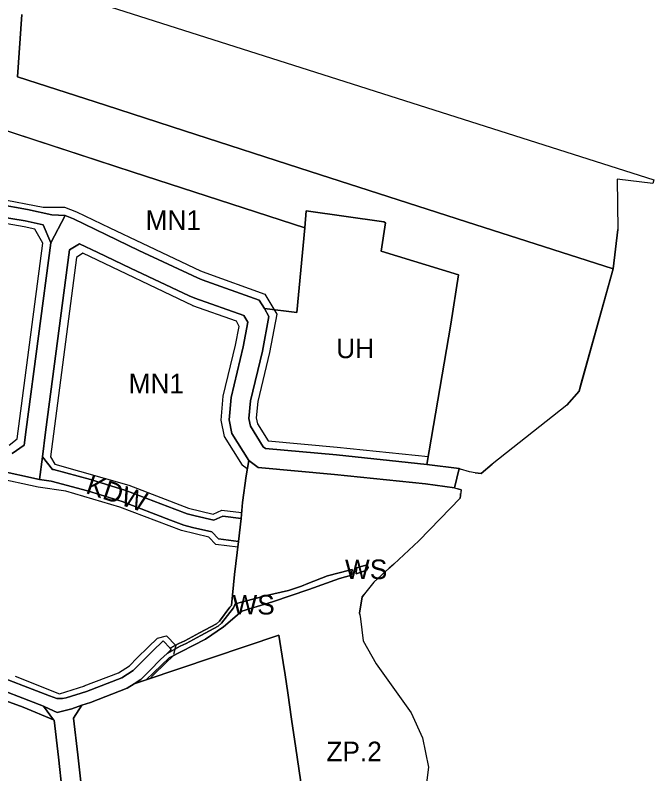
# Model space of a CAD drawing. Extents: x 7417187 to 7419415, y 5539178 to 5540826.
# Drawn here: x 7419039.6 to 7419365.1, y 5539846.6 to 5540233.3 of the extents above; entities that cross this region are included whole.
import ezdxf

# ---------------------------------------------------------------- set-up
doc = ezdxf.new("R2010")
doc.units = 0
for name, color, linetype in [('linie_rozgraniczajace', 7, 'Continuous'), ('linie_zabudowy_nieprzekraczalne', 7, 'Continuous'), ('oznaczenia_przeznaczen', 7, 'Continuous')]:
    doc.layers.add(name, color=color, linetype=linetype)

msp = doc.modelspace()

# ---------------------------------------------------------------- linework, layer by layer
at = {"layer": 'linie_rozgraniczajace'}
for p, q in [((7418953.71, 5540280.42), (7419365.07, 5540149.32)), ((7419040.73, 5540201.92), (7419042.99, 5540233.61)), ((7419042.99, 5540233.61), (7419040.73, 5540201.92)), ((7419085.71, 5540187.37), (7419040.73, 5540201.92)), ((7419040.73, 5540201.92), (7419085.71, 5540187.37)), ((7419125.94, 5540174.36), (7419085.71, 5540187.37)), ((7419085.71, 5540187.37), (7419125.94, 5540174.36)), ((7419099.77, 5540153.28), (7419009.97, 5540182.65)), ((7419189.96, 5540153.67), (7419125.94, 5540174.36)), ((7419125.94, 5540174.36), (7419189.96, 5540153.67)), ((7419187.3, 5540124.89), (7419099.77, 5540153.28)), ((7419269.53, 5540127.96), (7419189.96, 5540153.67)), ((7419189.96, 5540153.67), (7419269.53, 5540127.96)), ((7419364.59, 5540147.43), (7419346.47, 5540149.69)), ((7419346.47, 5540149.69), (7419346.66, 5540124.04)), ((7419365.07, 5540149.32), (7419364.59, 5540147.43)), ((7419187.88, 5540133.63), (7419187.3, 5540124.89)), ((7419227.45, 5540128), (7419187.88, 5540133.63)), ((7419226.14, 5540113.01), (7419228.27, 5540127.52)), ((7419228.27, 5540127.52), (7419227.45, 5540128)), ((7419344.29, 5540103.93), (7419269.53, 5540127.96)), ((7419269.53, 5540127.96), (7419344.29, 5540103.93)), ((7419346.66, 5540124.04), (7419344.29, 5540103.93)), ((7419344.29, 5540103.93), (7419346.66, 5540124.04)), ((7419346.66, 5540124.04), (7419344.29, 5540103.91)), ((7419265.58, 5540100.95), (7419226.14, 5540113.01)), ((7419344.29, 5540103.91), (7419326.95, 5540041.57)), ((7419344.29, 5540103.93), (7419327.75, 5540044.48)), ((7419327.75, 5540044.48), (7419344.29, 5540103.91)), ((7419344.29, 5540103.91), (7419344.29, 5540103.93)), ((7419261.62, 5540075.72), (7419265.58, 5540100.95)), ((7419249.35, 5540004.33), (7419261.62, 5540075.72)), ((7419326.99, 5540041.72), (7419327.75, 5540044.48)), ((7419327.75, 5540044.48), (7419326.99, 5540041.72)), ((7419326.95, 5540041.57), (7419320.75, 5540034.55)), ((7419320.75, 5540034.55), (7419326.95, 5540041.57)), ((7419326.95, 5540041.57), (7419320.75, 5540034.55)), ((7419326.95, 5540041.57), (7419326.99, 5540041.72)), ((7419326.99, 5540041.72), (7419326.95, 5540041.57)), ((7419320.75, 5540034.55), (7419282.67, 5540004.35)), ((7419157.28, 5539998.44), (7419158.63, 5540006.28)), ((7419158.63, 5540006.28), (7419163.52, 5540002.66)), ((7419163.52, 5540002.66), (7419202.39, 5539999.21)), ((7419265.81, 5540002.21), (7419249.35, 5540004.33)), ((7419265.81, 5540002.21), (7419263.58, 5539992.41)), ((7419263.58, 5539992.41), (7419265.81, 5540002.21)), ((7419266.52, 5540001.97), (7419265.81, 5540002.21)), ((7419265.81, 5540002.21), (7419266.52, 5540001.97)), ((7419266.52, 5540001.97), (7419265.81, 5540002.21)), ((7419271.11, 5540000.46), (7419266.52, 5540001.97)), ((7419282.67, 5540004.35), (7419277.05, 5539999.71)), ((7419277.05, 5539999.71), (7419282.67, 5540004.35)), ((7419282.67, 5540004.35), (7419277.05, 5539999.71)), ((7419155.44, 5539984.94), (7419157.28, 5539998.44)), ((7419202.39, 5539999.21), (7419248.75, 5539994.34)), ((7419274.04, 5540000.09), (7419271.11, 5540000.46)), ((7419277.05, 5539999.71), (7419274.04, 5540000.09)), ((7419277.05, 5539999.71), (7419274.04, 5540000.09)), ((7419274.04, 5540000.09), (7419277.05, 5539999.71)), ((7419248.75, 5539994.34), (7419263.58, 5539992.41)), ((7419263.58, 5539992.41), (7419263.58, 5539992.41)), ((7419263.58, 5539992.41), (7419265.23, 5539991.87)), ((7419265.23, 5539991.87), (7419266.89, 5539991.32)), ((7419266.89, 5539991.32), (7419265.23, 5539991.87)), ((7419265.23, 5539991.87), (7419266.89, 5539991.32)), ((7419266.35, 5539987.16), (7419256.18, 5539976.58)), ((7419266.35, 5539987.16), (7419256.18, 5539976.58)), ((7419256.18, 5539976.58), (7419266.35, 5539987.16)), ((7419266.64, 5539989.41), (7419266.35, 5539987.16)), ((7419266.51, 5539988.44), (7419266.35, 5539987.16)), ((7419266.35, 5539987.16), (7419266.51, 5539988.44)), ((7419266.64, 5539989.41), (7419266.51, 5539988.44)), ((7419266.51, 5539988.44), (7419266.64, 5539989.41)), ((7419154.75, 5539976.78), (7419155.44, 5539984.94)), ((7419153.45, 5539965.06), (7419154.75, 5539976.78)), ((7419256.18, 5539976.58), (7419245.31, 5539965.31)), ((7419256.18, 5539976.58), (7419245.31, 5539965.31)), ((7419245.31, 5539965.31), (7419256.18, 5539976.58)), ((7419151.33, 5539948.18), (7419153.45, 5539965.06)), ((7419245.31, 5539965.31), (7419232.56, 5539953.41)), ((7419245.31, 5539965.31), (7419232.56, 5539953.41)), ((7419232.56, 5539953.41), (7419245.31, 5539965.31)), ((7419213.56, 5539951.52), (7419213.39, 5539948.58)), ((7419218.94, 5539953.17), (7419213.56, 5539951.52)), ((7419218.6, 5539950.37), (7419219.44, 5539951.71)), ((7419219.44, 5539951.71), (7419218.94, 5539953.17)), ((7419230.26, 5539951.36), (7419222.43, 5539944.35)), ((7419232.56, 5539953.41), (7419230.26, 5539951.36)), ((7419230.49, 5539951.56), (7419230.26, 5539951.36)), ((7419230.26, 5539951.36), (7419230.49, 5539951.56)), ((7419232.56, 5539953.41), (7419230.49, 5539951.56)), ((7419230.49, 5539951.56), (7419232.56, 5539953.41)), ((7419149.86, 5539932.35), (7419151.33, 5539948.18)), ((7419198.73, 5539947.49), (7419188.69, 5539943.59)), ((7419209.91, 5539950.4), (7419198.73, 5539947.49)), ((7419204.89, 5539946.22), (7419211.08, 5539947.94)), ((7419211.27, 5539950.81), (7419209.91, 5539950.4)), ((7419211.08, 5539947.94), (7419211.27, 5539950.81)), ((7419213.39, 5539948.58), (7419214.91, 5539949)), ((7419214.91, 5539949), (7419218.6, 5539950.37)), ((7419188.69, 5539943.59), (7419185.46, 5539942.26)), ((7419189.3, 5539940.52), (7419204.89, 5539946.22)), ((7419222.43, 5539944.35), (7419217.63, 5539938.3)), ((7419178.91, 5539940.12), (7419167.69, 5539937.51)), ((7419170.7, 5539934.34), (7419189.3, 5539940.52)), ((7419185.46, 5539942.26), (7419178.91, 5539940.12)), ((7419167.69, 5539937.51), (7419155.72, 5539934.3)), ((7419216.52, 5539936.9), (7419215.12, 5539928.42)), ((7419216.52, 5539936.9), (7419215.12, 5539928.42)), ((7419215.12, 5539928.42), (7419216.52, 5539936.9)), ((7419217.63, 5539938.3), (7419216.52, 5539936.9)), ((7419217.43, 5539938.05), (7419216.52, 5539936.9)), ((7419216.52, 5539936.9), (7419217.43, 5539938.05)), ((7419217.63, 5539938.3), (7419217.43, 5539938.05)), ((7419217.43, 5539938.05), (7419217.63, 5539938.3)), ((7419149.02, 5539931.48), (7419149.86, 5539932.35)), ((7419151.76, 5539933.27), (7419150.82, 5539931.15)), ((7419155.72, 5539934.3), (7419151.76, 5539933.27)), ((7419155.11, 5539929.59), (7419170.7, 5539934.34)), ((7419143.68, 5539924.38), (7419149.02, 5539931.48)), ((7419150.82, 5539931.15), (7419144.8, 5539923.37)), ((7419145.85, 5539921.58), (7419155.11, 5539929.59)), ((7419215.12, 5539928.42), (7419215.12, 5539928.42)), ((7419215.12, 5539928.42), (7419215.21, 5539927.85)), ((7419215.12, 5539928.42), (7419215.12, 5539928.42)), ((7419215.12, 5539928.42), (7419215.21, 5539927.85)), ((7419215.21, 5539927.85), (7419215.12, 5539928.42)), ((7419142.26, 5539923.02), (7419143.68, 5539924.38)), ((7419215.21, 5539927.85), (7419215.59, 5539925.62)), ((7419215.59, 5539925.62), (7419216.9, 5539914.34)), ((7419133.48, 5539918.5), (7419142.26, 5539923.02)), ((7419143.14, 5539921.79), (7419134.18, 5539917.17)), ((7419136.54, 5539915.24), (7419145.85, 5539921.58)), ((7419144.8, 5539923.37), (7419143.14, 5539921.79)), ((7419174.03, 5539917.24), (7419106.41, 5539894.54)), ((7419126.05, 5539914.46), (7419133.48, 5539918.5)), ((7419134.18, 5539917.17), (7419126.72, 5539913.11)), ((7419176.19, 5539903.36), (7419174.03, 5539917.24)), ((7419118.13, 5539905.71), (7419136.54, 5539915.24)), ((7419118.62, 5539910.59), (7419123.01, 5539913.09)), ((7419123.01, 5539913.09), (7419126.05, 5539914.46)), ((7419126.72, 5539913.11), (7419123.69, 5539911.75)), ((7419216.9, 5539914.34), (7419223.57, 5539902.66)), ((7419123.69, 5539911.75), (7419117, 5539907.94)), ((7419117, 5539907.94), (7419119.17, 5539910.02)), ((7419119.17, 5539910.02), (7419118.62, 5539910.59)), ((7419106.41, 5539894.54), (7419118.13, 5539905.71)), ((7419177.17, 5539896.99), (7419176.19, 5539903.36)), ((7419223.57, 5539902.66), (7419241.45, 5539877.63)), ((7419178.5, 5539887.94), (7419177.17, 5539896.99)), ((7419180.45, 5539874.45), (7419178.5, 5539887.94)), ((7419241.45, 5539877.63), (7419247.22, 5539864.94)), ((7419182.59, 5539859.62), (7419180.45, 5539874.45)), ((7419247.22, 5539864.94), (7419250.22, 5539850.01)), ((7419185.79, 5539837.72), (7419182.59, 5539859.62)), ((7419250.22, 5539850.01), (7419249.03, 5539840.61))]:
    msp.add_line(p, q, dxfattribs=at)
for points in [[(7419009.97, 5540182.65), (7419099.77, 5540153.28), (7419187.3, 5540124.89), (7419183.16, 5540081.78), (7419166.6, 5540083.72), (7419164.04, 5540088.08), (7419134.86, 5540098.32), (7419132.48, 5540099.36), (7419102.61, 5540113.38), (7419086.16, 5540121.29), (7419069.34, 5540129.44), (7419065.02, 5540131.1), (7419058.27, 5540131.55), (7419045.91, 5540134.3), (7419030.57, 5540136.87)], [(7419030.57, 5540136.87), (7419045.91, 5540134.3), (7419058.27, 5540131.55), (7419065.02, 5540131.1), (7419057.79, 5540117.26), (7419053.89, 5540126.4), (7419044.7, 5540128.42), (7419029.99, 5540130.9)], [(7419029.99, 5540130.9), (7419044.7, 5540128.42), (7419053.89, 5540126.4), (7419057.79, 5540117.26), (7419045.21, 5540022.08), (7419044.21, 5540014.19), (7419038.11, 5540009.87)], [(7419038.11, 5540009.87), (7419044.21, 5540014.19), (7419045.21, 5540022.08), (7419057.79, 5540117.26), (7419065.02, 5540131.1), (7419069.34, 5540129.44), (7419086.16, 5540121.29), (7419102.61, 5540113.38), (7419132.48, 5540099.36), (7419134.86, 5540098.32), (7419164.04, 5540088.08), (7419166.6, 5540083.72), (7419168.93, 5540079.77), (7419165.58, 5540062.1), (7419159.54, 5540036.74), (7419158.69, 5540027.63), (7419159.49, 5540023.81), (7419166.05, 5540013.22), (7419167.2, 5540012.38), (7419203.35, 5540009.16), (7419249.35, 5540004.33), (7419265.81, 5540002.21), (7419263.58, 5539992.41), (7419248.75, 5539994.34), (7419202.39, 5539999.21), (7419163.52, 5540002.66), (7419158.63, 5540006.28), (7419150.06, 5540020.04), (7419148.6, 5540027.06), (7419149.65, 5540038.37), (7419155.8, 5540064.19), (7419158.19, 5540076.8), (7419156.16, 5540080.25), (7419131.19, 5540089.01), (7419128.35, 5540090.25), (7419098.32, 5540104.35), (7419081.81, 5540112.28), (7419072.47, 5540116.81), (7419067.39, 5540113.62), (7419055.12, 5540020.79), (7419053.54, 5540008.24), (7419052.07, 5539996.64), (7419051.98, 5539996.65), (7419030.26, 5540001.34)], [(7419030.26, 5540001.34), (7419051.98, 5539996.65), (7419052.07, 5539996.64), (7419057.95, 5539995.77), (7419076.43, 5539990.84), (7419094.12, 5539985.36), (7419118.75, 5539975.96), (7419125.51, 5539973.32), (7419129.92, 5539972.22), (7419139.78, 5539969.93), (7419143.28, 5539966.35), (7419153.45, 5539965.06), (7419151.33, 5539948.18), (7419149.86, 5539932.35), (7419149.02, 5539931.48), (7419143.68, 5539924.38), (7419142.26, 5539923.02), (7419133.48, 5539918.5), (7419126.05, 5539914.46), (7419123.01, 5539913.09), (7419118.62, 5539910.59), (7419115.02, 5539914.35), (7419109.53, 5539909.09), (7419103.93, 5539903.54), (7419099.83, 5539899.31), (7419094.01, 5539895.61), (7419075.96, 5539888.61), (7419065.68, 5539885.34), (7419063.76, 5539885.06), (7419060.91, 5539885.08), (7419057.16, 5539886.31), (7419025.25, 5539898.66)], [(7418705.75, 5539931.19), (7418748.43, 5539931.6), (7418756.83, 5539934.88), (7418779.73, 5539935.88), (7418838.4, 5539938.54), (7418861.65, 5539939.62), (7418902.71, 5539935.29), (7418948.05, 5539929.8), (7418949.36, 5539928.49), (7418958.82, 5539916.51), (7418967.84, 5539910.9), (7418990.65, 5539900.55), (7419019.82, 5539889.33), (7419043.74, 5539880.5), (7419059.22, 5539874.18), (7419059.44, 5539873.89), (7419061.66, 5539855.14), (7419063.63, 5539837.78)], [(7419025.25, 5539898.66), (7419057.16, 5539886.31), (7419060.91, 5539885.08), (7419063.76, 5539885.06), (7419065.68, 5539885.34), (7419075.96, 5539888.61), (7419094.01, 5539895.61), (7419099.83, 5539899.31), (7419103.93, 5539903.54), (7419109.53, 5539909.09), (7419115.02, 5539914.35), (7419118.62, 5539910.59), (7419119.17, 5539910.02), (7419117, 5539907.94), (7419113.72, 5539904.8), (7419108.2, 5539899.32), (7419103.65, 5539894.63), (7419100.27, 5539892.48), (7419096.73, 5539890.23), (7419077.96, 5539882.95), (7419073.55, 5539881.54), (7419068.52, 5539879.81), (7419060.97, 5539877.95), (7419054.82, 5539880.78), (7419054.07, 5539881.07), (7419023.14, 5539893.05)], [(7419023.14, 5539893.05), (7419054.07, 5539881.07), (7419059.22, 5539874.18), (7419043.74, 5539880.5), (7419019.82, 5539889.33)], [(7419063.63, 5539837.78), (7419061.66, 5539855.14), (7419059.44, 5539873.89), (7419059.22, 5539874.18), (7419054.07, 5539881.07), (7419054.82, 5539880.78), (7419060.97, 5539877.95), (7419068.52, 5539879.81), (7419073.55, 5539881.54), (7419069.37, 5539875.06), (7419071.59, 5539856.29), (7419073.67, 5539837.92)]]:
    msp.add_lwpolyline(points, dxfattribs=at)
for points in [[(7419249.35, 5540004.33), (7419203.35, 5540009.16), (7419167.2, 5540012.38), (7419166.05, 5540013.22), (7419159.49, 5540023.81), (7419158.69, 5540027.63), (7419159.54, 5540036.74), (7419165.58, 5540062.1), (7419168.93, 5540079.77), (7419166.6, 5540083.72), (7419183.16, 5540081.78), (7419187.3, 5540124.89), (7419187.88, 5540133.63), (7419227.45, 5540128), (7419228.27, 5540127.52), (7419226.14, 5540113.01), (7419265.58, 5540100.95), (7419261.62, 5540075.72)], [(7419158.63, 5540006.28), (7419157.28, 5539998.44), (7419155.44, 5539984.94), (7419154.75, 5539976.78), (7419145.37, 5539977.91), (7419140.91, 5539975.82), (7419131.33, 5539978.05), (7419127.34, 5539979.05), (7419120.91, 5539981.56), (7419096.08, 5539991.03), (7419078.09, 5539996.61), (7419059.16, 5540001.66), (7419058.57, 5540001.74), (7419053.54, 5540008.24), (7419055.12, 5540020.79), (7419067.39, 5540113.62), (7419072.47, 5540116.81), (7419081.81, 5540112.28), (7419098.32, 5540104.35), (7419128.35, 5540090.25), (7419131.19, 5540089.01), (7419156.16, 5540080.25), (7419158.19, 5540076.8), (7419155.8, 5540064.19), (7419149.65, 5540038.37), (7419148.6, 5540027.06), (7419150.06, 5540020.04)], [(7419154.75, 5539976.78), (7419153.45, 5539965.06), (7419143.28, 5539966.35), (7419139.78, 5539969.93), (7419129.92, 5539972.22), (7419125.51, 5539973.32), (7419118.75, 5539975.96), (7419094.12, 5539985.36), (7419076.43, 5539990.84), (7419057.95, 5539995.77), (7419052.07, 5539996.64), (7419053.54, 5540008.24), (7419058.57, 5540001.74), (7419059.16, 5540001.66), (7419078.09, 5539996.61), (7419096.08, 5539991.03), (7419120.91, 5539981.56), (7419127.34, 5539979.05), (7419131.33, 5539978.05), (7419140.91, 5539975.82), (7419145.37, 5539977.91)], [(7419214.91, 5539949), (7419213.39, 5539948.58), (7419213.56, 5539951.52), (7419218.94, 5539953.17), (7419219.44, 5539951.71), (7419218.6, 5539950.37)], [(7419106.41, 5539894.54), (7419100.27, 5539892.48), (7419103.65, 5539894.63), (7419108.2, 5539899.32), (7419113.72, 5539904.8), (7419117, 5539907.94), (7419123.69, 5539911.75), (7419126.72, 5539913.11), (7419134.18, 5539917.17), (7419143.14, 5539921.79), (7419144.8, 5539923.37), (7419150.82, 5539931.15), (7419151.76, 5539933.27), (7419155.72, 5539934.3), (7419167.69, 5539937.51), (7419178.91, 5539940.12), (7419185.46, 5539942.26), (7419188.69, 5539943.59), (7419198.73, 5539947.49), (7419209.91, 5539950.4), (7419211.27, 5539950.81), (7419211.08, 5539947.94), (7419204.89, 5539946.22), (7419189.3, 5539940.52), (7419170.7, 5539934.34), (7419155.11, 5539929.59), (7419145.85, 5539921.58), (7419136.54, 5539915.24), (7419118.13, 5539905.71)], [(7419148.72, 5539779.71), (7419082.92, 5539766.9), (7419081.88, 5539777.49), (7419079.76, 5539798.03), (7419076.8, 5539817.26), (7419073.67, 5539837.92), (7419071.59, 5539856.29), (7419069.37, 5539875.06), (7419073.55, 5539881.54), (7419077.96, 5539882.95), (7419096.73, 5539890.23), (7419100.27, 5539892.48), (7419106.41, 5539894.54), (7419174.03, 5539917.24), (7419176.19, 5539903.36), (7419177.17, 5539896.99), (7419178.5, 5539887.94), (7419180.45, 5539874.45), (7419182.59, 5539859.62), (7419185.79, 5539837.72), (7419188.75, 5539817.33), (7419192.83, 5539788.1), (7419151.48, 5539780.24)]]:
    msp.add_lwpolyline(points, close=True, dxfattribs=at)
msp.add_open_spline([(7419266.89, 5539991.32), (7419266.64, 5539989.41)], degree=1, dxfattribs=at)
at = {"layer": 'linie_zabudowy_nieprzekraczalne'}
for points in [[(7418900.67, 5540133.79), (7418963.86, 5540140.82), (7419003.54, 5540142.07), (7419030.8, 5540139.86), (7419053.93, 5540135.47)], [(7419053.93, 5540135.47), (7419064.72, 5540135.5)], [(7419064.72, 5540135.5), (7419070.93, 5540133.12), (7419087.9, 5540124.89), (7419104.33, 5540117), (7419134.14, 5540103), (7419136.72, 5540101.87)], [(7419049.6, 5540124.28), (7419044.13, 5540125.48), (7419029.63, 5540127.92), (7419023.82, 5540128.35)], [(7419053.72, 5540117.02), (7419049.6, 5540124.28)], [(7419040.61, 5540017.43), (7419053.72, 5540117.02)], [(7419070.92, 5540109.79), (7419057.56, 5540008.16)], [(7419074.18, 5540111.92), (7419070.92, 5540109.79)], [(7419130.3, 5540085.08), (7419074.18, 5540111.92)], [(7419136.7, 5540101.88), (7419166.89, 5540091.12)], [(7419166.89, 5540091.12), (7419172.89, 5540080.92)], [(7419152.48, 5540077.3), (7419130.08, 5540085.16)], [(7419172.89, 5540080.92), (7419169.17, 5540061.3), (7419163.23, 5540036.36), (7419162.43, 5540028.05), (7419163.1, 5540024.97), (7419168.49, 5540016.28)], [(7419153.72, 5540074.68), (7419152.48, 5540077.3)], [(7419155.39, 5540003.87), (7419146.29, 5540018.53), (7419144.56, 5540026.83), (7419145.7, 5540039.02), (7419151.89, 5540065.03), (7419153.72, 5540074.68)], [(7419036.62, 5540014.15), (7419040.61, 5540017.43)], [(7419168.49, 5540016.28), (7419203.74, 5540013.14), (7419250.03, 5540008.28)], [(7419057.56, 5540008.16), (7419059.92, 5540004.45)], [(7419059.92, 5540004.45), (7419097.54, 5539993.69), (7419127.9, 5539982.06), (7419140.53, 5539978.96)], [(7419157.9, 5540002.01), (7419155.32, 5540003.98)], [(7419065.49, 5539990.62), (7419051.27, 5539992.72), (7419029.34, 5539997.45)], [(7419138.25, 5539967.21), (7419124.36, 5539970.56), (7419093.02, 5539982.56), (7419065.49, 5539990.62)], [(7419140.53, 5539978.96), (7419144.88, 5539980.99), (7419154.98, 5539979.78)], [(7419153.08, 5539962.09), (7419141.87, 5539963.51), (7419138.25, 5539967.21)], [(7419112.22, 5539915.83), (7419116.77, 5539916.92)], [(7419116.77, 5539916.92), (7419121.46, 5539911.99)], [(7419092.32, 5539898.09), (7419097.93, 5539901.65), (7419101.8, 5539905.65), (7419107.44, 5539911.24), (7419112.22, 5539915.83)], [(7419121.46, 5539911.99), (7419120.3, 5539907.4)], [(7419120.53, 5539907.17), (7419115.82, 5539902.65), (7419110.33, 5539897.22), (7419108.17, 5539894.98)], [(7419074.85, 5539891.4), (7419092.32, 5539898.09)], [(7419039.65, 5539896.31), (7419062.25, 5539887.4)], [(7419062.25, 5539887.4), (7419075.08, 5539891.48)]]:
    msp.add_lwpolyline(points, dxfattribs=at)

# ---------------------------------------------------------------- texts
at = {"layer": 'oznaczenia_przeznaczen'}
for s, p in [('MN1', (7419106.08, 5540123.8)), ('UH', (7419203.21, 5540058.46)), ('MN1', (7419097.46, 5540040.55)), ('WS', (7419207.7, 5539945.83)), ('WS', (7419150.36, 5539927.82)), ('ZP.2', (7419198.22, 5539853))]:
    msp.add_text(s, height=10, dxfattribs=at).set_placement(p)
msp.add_text('KDW', height=10, rotation=341.4998, dxfattribs=at).set_placement((7419075.07, 5539989.81))

doc.saveas('drawing.dxf')
